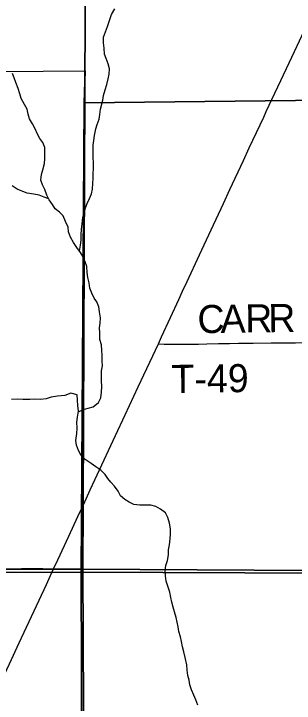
# Model space of a CAD drawing. Extents: x 0 to 34, y 0 to 22.
# Drawn here: x 5.628 to 6.195, y 15 to 16.396 of the extents above; entities that cross this region are included whole.
import ezdxf

# ---------------------------------------------------------------- set-up
doc = ezdxf.new("R2010")
doc.units = 0
for name, color, linetype in [('GM_X_Minor_River', 7, 'Continuous'), ('GM_X_Section', 7, 'Continuous'), ('GM_X_State_Route', 7, 'Continuous'), ('GM_X_Township_Road', 7, 'Continuous'), ('GM_X_Township_Road_Text', 7, 'Continuous')]:
    doc.layers.add(name, color=color, linetype=linetype)

msp = doc.modelspace()

# ---------------------------------------------------------------- linework, layer by layer
at = {"layer": 'GM_X_Minor_River'}
for points in [[(5.7605, 15.9152), (5.7625, 15.9268), (5.7637, 15.9371), (5.7637, 15.9477), (5.7649, 15.9598), (5.7657, 15.9704), (5.7676, 15.9833), (5.7703, 15.9932), (5.7726, 16.0027), (5.7764, 16.0114), (5.781, 16.0216), (5.7848, 16.0311), (5.7871, 16.0405), (5.7876, 16.0523), (5.7884, 16.0618), (5.7884, 16.0713), (5.7888, 16.0823), (5.7892, 16.0929), (5.7885, 16.1054), (5.7882, 16.1168), (5.7882, 16.1293), (5.7898, 16.1388), (5.791, 16.1494), (5.7937, 16.1623), (5.7963, 16.1714), (5.8002, 16.1824), (5.8017, 16.1919), (5.8033, 16.2021), (5.8075, 16.2203), (5.809, 16.2298), (5.8125, 16.2415), (5.8156, 16.2525), (5.8186, 16.2635), (5.8209, 16.2734), (5.821, 16.284), (5.8187, 16.2942), (5.8142, 16.3049), (5.8113, 16.314), (5.8105, 16.3258), (5.8091, 16.3368), (5.8091, 16.3485), (5.8129, 16.3588), (5.8175, 16.3697), (5.8213, 16.3819), (5.8252, 16.3944), (5.832, 16.4057)], [(5.7584, 15.5897), (5.7688, 15.5944), (5.7783, 15.5974), (5.7881, 15.6), (5.7991, 15.6087), (5.8037, 15.6181), (5.8052, 15.6295), (5.8057, 15.6413), (5.8049, 15.6523), (5.805, 15.6625), (5.805, 15.6728), (5.807, 15.6826), (5.8066, 15.6925), (5.8063, 15.7043), (5.8059, 15.7138), (5.8048, 15.7251), (5.8019, 15.7362), (5.8015, 15.7498), (5.8012, 15.7597), (5.8024, 15.7695), (5.8028, 15.7802), (5.8013, 15.7919), (5.7998, 15.8022), (5.7957, 15.8125), (5.7901, 15.8201), (5.7852, 15.83), (5.7815, 15.8398), (5.78, 15.8509), (5.7774, 15.8619), (5.7759, 15.8717), (5.7752, 15.8839), (5.7722, 15.8934), (5.7681, 15.9033), (5.7625, 15.9124), (5.7553, 15.9227), (5.7485, 15.9322), (5.7425, 15.9432), (5.7384, 15.9539), (5.7373, 15.9634), (5.7324, 15.9752), (5.7276, 15.9866), (5.72, 15.9938), (5.711, 16.0007), (5.7061, 16.0094), (5.6993, 16.019), (5.6945, 16.0285), (5.6903, 16.0395), (5.6858, 16.049), (5.6821, 16.0585), (5.6836, 16.0699), (5.6863, 16.0794), (5.6898, 16.0926), (5.6906, 16.1025), (5.6906, 16.1131), (5.6903, 16.1245), (5.6865, 16.1347), (5.6805, 16.1427), (5.6753, 16.1515), (5.6708, 16.1625), (5.6655, 16.1724), (5.6595, 16.1827), (5.6565, 16.1926), (5.655, 16.2021), (5.6494, 16.212), (5.6426, 16.2238), (5.6396, 16.2333), (5.6363, 16.2443), (5.6318, 16.2561), (5.6284, 16.2656), (5.6247, 16.2743)], [(5.6985, 16.0206), (5.6891, 16.0243), (5.6789, 16.0282), (5.668, 16.0305), (5.6548, 16.0321), (5.6461, 16.0359), (5.6344, 16.0405), (5.6242, 16.047)], [(5.7937, 15.4786), (5.7839, 15.4851), (5.7718, 15.4935), (5.7639, 15.5011), (5.7583, 15.5117), (5.7545, 15.522), (5.7534, 15.5315), (5.7554, 15.5455), (5.7558, 15.5565), (5.7555, 15.5687), (5.7566, 15.5789), (5.7586, 15.5907), (5.7571, 15.6024), (5.7568, 15.6131), (5.7561, 15.6244), (5.7432, 15.6275), (5.7307, 15.6227), (5.716, 15.6212), (5.7035, 15.6194), (5.6929, 15.616), (5.6815, 15.6149), (5.6694, 15.6154), (5.66, 15.6147), (5.646, 15.6147), (5.6343, 15.6152), (5.6229, 15.6148)], [(5.9998, 14.9961), (5.9961, 15.0063), (5.992, 15.0158), (5.9871, 15.0268), (5.9837, 15.0371), (5.9822, 15.0466), (5.98, 15.0561), (5.9782, 15.0667), (5.9775, 15.0777), (5.9741, 15.0922), (5.9715, 15.1036), (5.9693, 15.1138), (5.9667, 15.1245), (5.9648, 15.134), (5.9618, 15.145), (5.9603, 15.1545), (5.9581, 15.164), (5.9559, 15.1735), (5.9525, 15.1845), (5.9499, 15.1944), (5.9473, 15.2042), (5.9455, 15.2137), (5.9436, 15.2244), (5.9399, 15.235), (5.9361, 15.2468), (5.9347, 15.2578), (5.9339, 15.268), (5.9355, 15.2783), (5.9386, 15.2889), (5.9405, 15.3003), (5.9409, 15.3105), (5.9428, 15.3207), (5.944, 15.3329), (5.9444, 15.3427), (5.9448, 15.3526), (5.9426, 15.364), (5.9393, 15.3758), (5.9344, 15.3853), (5.9246, 15.3929), (5.9151, 15.3983), (5.9046, 15.4006), (5.8936, 15.4007), (5.8826, 15.4007), (5.8702, 15.4023), (5.8611, 15.4065), (5.8521, 15.4123), (5.8438, 15.4195), (5.8385, 15.4294), (5.8314, 15.4389), (5.8242, 15.4473), (5.8178, 15.4545), (5.8125, 15.4625), (5.8035, 15.4713), (5.7937, 15.4786)]]:
    msp.add_lwpolyline(points, dxfattribs=at)
at = {"layer": 'GM_X_Section'}
for points in [[(4.7564, 16.8709), (4.754, 16.2718), (5.7718, 16.2797), (5.7724, 17.2281), (5.7727, 17.3042), (4.804, 17.2765), (4.804, 16.8709)], [(5.7724, 17.2281), (6.9237, 17.2428), (6.9303, 16.2282), (5.7699, 16.2149), (5.7718, 16.2797)], [(5.7718, 16.2797), (5.7699, 16.2149), (5.7637, 15.2651), (4.743, 15.2637), (4.754, 16.2718)], [(6.9303, 16.2282), (6.9228, 15.2602), (5.7637, 15.2651), (5.7699, 16.2149)], [(5.7637, 15.2651), (5.7673, 14.2653), (4.7506, 14.2503), (4.743, 15.2637)], [(6.9531, 15.2604), (6.9669, 14.2596), (5.7673, 14.2653), (5.7637, 15.2651), (6.9228, 15.2602)]]:
    msp.add_lwpolyline(points, close=True, dxfattribs=at)
at = {"layer": 'GM_X_State_Route'}
for points in [[(5.7684, 15.4016), (5.7823, 15.4315), (5.8059, 15.4823), (5.8243, 15.5218), (5.8334, 15.5416), (5.8532, 15.5839), (5.8795, 15.6403), (5.9203, 15.7275), (5.9267, 15.7415), (5.945, 15.7808), (5.9617, 15.817), (5.9692, 15.834), (5.9782, 15.8538), (6.0033, 15.9072), (6.0268, 15.958), (6.0518, 16.0114), (6.0649, 16.0396), (6.0923, 16.0988), (6.104, 16.1241), (6.1334, 16.1864), (6.1386, 16.1977), (6.1794, 16.285), (6.2217, 16.3749)], [(5.7075, 15.2708), (5.717, 15.2901), (5.739, 15.3382), (5.7573, 15.3778), (5.7684, 15.4016)], [(5.5686, 14.9763), (5.592, 15.0236), (5.6188, 15.0798), (5.6385, 15.1221), (5.6937, 15.2404), (5.7075, 15.2708)]]:
    msp.add_lwpolyline(points, dxfattribs=at)
at = {"layer": 'GM_X_Township_Road'}
msp.add_lwpolyline([(5.7705, 14.1), (8.9, 14.1), (8.9, 17.2634), (8.4218, 17.2637), (7.9163, 17.252), (7.9297, 16.3619), (7.9298, 16.2686), (7.9298, 16.2367), (7.9301, 16.1134), (7.9306, 15.7658), (7.9283, 15.2595), (6.9226, 15.2644), (5.7675, 15.2711), (5.7694, 14.855)], close=True, dxfattribs=at)
for points in [[(5.6119, 15.2714), (5.643, 15.2716), (5.6865, 15.2717), (5.7073, 15.2713), (5.7675, 15.2711), (5.7682, 15.4021), (5.7732, 16.7342)], [(5.7732, 16.7342), (5.7682, 15.4021), (5.7675, 15.2711), (6.9226, 15.2644)], [(5.9203, 15.7275), (5.9321, 15.7269), (5.9399, 15.7266), (5.9448, 15.7267), (5.963, 15.7266), (5.9831, 15.7266), (5.9933, 15.7265), (6.0013, 15.7266), (6.018, 15.7271), (6.0416, 15.7278), (6.0638, 15.7281), (6.0821, 15.7284), (6.0974, 15.7286), (6.112, 15.7289), (6.1481, 15.7291), (6.1977, 15.7294), (6.2381, 15.7302), (6.2533, 15.731), (6.2615, 15.7313), (6.2643, 15.7315)], [(5.199, 15.2698), (5.2047, 15.2697), (5.2147, 15.27), (5.2269, 15.2701), (5.2483, 15.2698), (5.2615, 15.2695), (5.3029, 15.2696), (5.345, 15.2696), (5.3854, 15.2696), (5.4693, 15.2699), (5.4973, 15.27), (5.5283, 15.2703), (5.5439, 15.2704), (5.5594, 15.2706), (5.5904, 15.2708), (5.6121, 15.2708), (5.6432, 15.271), (5.6867, 15.2712), (5.7075, 15.2708)], [(5.7694, 14.855), (5.7675, 15.2711), (5.7073, 15.2713), (5.6865, 15.2717), (5.643, 15.2716), (5.6119, 15.2714)]]:
    msp.add_lwpolyline(points, dxfattribs=at)

# ---------------------------------------------------------------- texts
at = {"layer": 'GM_X_Township_Road_Text'}
for s, height, rotation, p in [('C', 0.0568, 0.8021, (5.9996, 15.7488)), ('A', 0.0568, 0.8036, (6.0463, 15.7495)), ('R', 0.0568, 0.8029, (6.0963, 15.7502)), ('R', 0.0568, 0.8049, (6.1429, 15.7508)), ('T-49', 0.05682, 0.7054, (5.947, 15.6278))]:
    msp.add_text(s, height=height, rotation=rotation, dxfattribs=at).set_placement(p)

doc.saveas('drawing.dxf')
